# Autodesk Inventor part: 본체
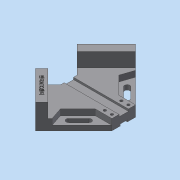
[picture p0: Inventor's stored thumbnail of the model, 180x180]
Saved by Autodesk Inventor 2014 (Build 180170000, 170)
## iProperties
Created: 2019-04
Part Number: 본체
Material: 일반
Document SubType Name: Modeling
Designer: 601-06
Density: 1 g/cm^3
Appearance: 기본값
Author: 601-06
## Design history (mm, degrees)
sketch "스케치4"
  geometry: L1 (-20, 0)-(0, 0); L2 (149.706, 0)-(114.35, -35.355); L3 (64.853, -84.853)-(0, -20); L4 (0, 0)-(0, -20); L5 (114.35, -35.355)-(93, -14.005); L6 (93, -14.005)-(93, 0); L7 (0, -20)-(-20, 0); L8 (114.35, -35.355)-(64.853, -84.853); L9 (93, 0)-(149.706, 0); L10 (0, 0)-(93, 0); L11 (93, 14.005)-(93, 0); L12 (114.35, 35.355)-(93, 14.005); L13 (114.35, 35.355)-(64.853, 84.853); L14 (64.853, 84.853)-(0, 20); L15 (0, 0)-(0, 20); 2 further points
  constraints: 30 end point, 12 perpendicular, 4 symmetric about line, 3 coincident, 3 horizontal
  dimensions: "d1" = 120 distance of L3.start L1.start; "d2" = 120 distance of L2.start L3.start; "d3" = 20 distance from line of L4 L1.start; "d5" = 93 distance between parallel lines of L4 L6; "d6" = 70 distance between parallel lines of L3 L5
extrude "돌출1" new body sketch "스케치4" distance "d7" = 18; taper "d8" = 0 deg
sketch "스케치5"
  geometry: L1 (-93, -14.005)-(-114.35, -35.355) reference; L2 (-114.35, -35.355)-(-64.853, -84.853) reference; L3 (-64.853, -84.853)-(0, -20) reference; L4 (0, 20)-(-64.853, 84.853) reference; L5 (-64.853, 84.853)-(-114.35, 35.355) reference; L6 (-114.35, 35.355)-(-93, 14.005) reference; L7 (-54.246, -74.246)-(-103.744, -24.749); L8 (-103.744, 24.749)-(-54.246, 74.246); 1 further point
  constraints: 4 end point, 4 point on line, 2 perpendicular
  dimensions: "d9" = 15 distance between parallel lines of L5 L8; "d10" = 15 distance between parallel lines of L2 L7
extrude "돌출2" join sketch "스케치5" distance "d11" = 24; taper "d12" = 0 deg
sketch "스케치6"
  geometry: L1 (-54.246, -74.246)-(0, -20) reference; L2 (0, -20)-(0, 20) reference; L3 (-93, 14.005)-(-93, -14.005) reference; L4 (-28.284, -20)-(-57.782, -49.497); L5 (-57.782, -49.497)-(-50.711, -70.711); L6 (0, -20)-(-28.284, -20); L7 (-114.35, -35.355)-(-64.853, -84.853) reference; 1 further point
  constraints: 6 end point, 2 point on line, 1 parallel, 1 perpendicular
  dimensions: "d13" = 20 distance between parallel lines of L4 L1; "d14" = 20 distance of L5.end L7.end; "d15" = 30 distance from line of L7 L4.end; "d16" = 20 distance from line of point (0, 0) L6
extrude "돌출3" cut sketch "스케치6" distance "d17" = 10; taper "d18" = 0 deg
sketch "스케치7"
  geometry: L1 (0, -20)-(-50.711, -70.711) reference; L2 (-26.669, -32.527)-(-43.64, -49.497); L3 (-29.851, -29.345)-(-46.822, -46.315); L4 (-40.458, -52.679)-(-23.487, -35.709); L5 (-114.35, -35.355)-(-64.853, -84.853) reference; A1 r 4.5 centre (-26.669, -32.527) between (-23.487, -35.709) and (-29.851, -29.345); A2 r 4.5 centre (-43.64, -49.497) between (-46.822, -46.315) and (-40.458, -52.679); 2 further points
  constraints: 8 end point, 4 point on circle, 4 tangent, 2 centre point, 2 parallel, 1 midpoint
  dimensions: "d19" = 9 distance between parallel lines of L3 L4; "d20" = 40 distance from line of L5 L2.end; "d21" = 24 distance of L2.start L2.end; "d22" = 10 distance between parallel lines of L1 L2
extrude "돌출4" cut sketch "스케치7" stored distance "d23" = 10; taper "d24" = 0 deg
sketch "스케치8"
  geometry: L1 (0, -20)-(0, 20) reference; C1 r 2.25 at (-6, -14); C2 r 2.25 at (-18, -14); 1 further point
  constraints: 2 centre point
  dimensions: "d25" = 4.5 diameter of C1; "d26" = 14 vertical distance of point (0, 0) C1.centre; "d27" = 6 distance from line of C1.centre L1; "d28" = 4.5 diameter of C2; "d29" = 14 vertical distance of point (0, 0) C2.centre; "d30" = 12 distance of C2.centre C1.centre
extrude "돌출5" cut sketch "스케치8" stored distance "d31" = 10; taper "d32" = 0 deg
sketch "스케치9"
  geometry: C1 r 2.25 at (-6, 14) reference; C2 r 2.25 at (-18, 14) reference; 1 further point
hole "구멍1" sketch "스케치9" at (-18, 14), (-6, 14) diameter "d33" = 8; stored, may be unused: countersink angle "d37" = 90 deg, drill point angle "d39" = 0 deg; dims "d34" = 6, "d35" = 4, "d36" = 2, "d38" = 10
sketch "스케치10"
  geometry: L1 (0, -20)-(0, 20) reference; L2 (-93, 14.005)-(-93, -14.005) reference; L3 (-93, -8)-(0, -8); L4 (0, -8)-(0, 8); L5 (0, 8)-(-93, 8); L6 (-93, 8)-(-93, -8); 1 further point
  constraints: 8 end point, 2 parallel, 2 point on line, 1 horizontal, 1 perpendicular
  dimensions: "d40" = 16 distance between parallel lines of L3 L5; "d41" = 8 distance from line of L5 point (0, 0)
extrude "돌출6" cut sketch "스케치10" distance "d42" = 3.5; taper "d43" = 0 deg
sketch "스케치11"
  geometry: L1 (0, 20)-(0, -20) reference; L2 (-93, -14.005)-(-93, 14.005) reference; L3 (-93, 6)-(0, 6); L4 (0, 6)-(0, -6); L5 (0, -6)-(-93, -6); L6 (-93, -6)-(-93, 6); 1 further point
  constraints: 8 end point, 2 parallel, 2 point on line, 1 horizontal, 1 perpendicular
  dimensions: "d44" = 12 distance between parallel lines of L3 L5; "d45" = 6 distance from line of point (0, 0) L5
extrude "돌출7" cut sketch "스케치11" distance "d46" = 3; taper "d47" = 0 deg
sketch "스케치12"
  geometry: L1 (-114.35, -35.355)-(-64.853, -84.853) reference; L2 (-64.853, -84.853)-(-54.246, -74.246) reference; 2 further points
  constraints: 1 other
  dimensions: "d48" = 35 distance from line of L2 point (-84.298, -54.801); "d50" = 7.5 distance from line of L1 point (-84.298, -54.801)
feature "엠보싱1" sketch "스케치12" dims "d1" = 120, "d2" = 120, "d3" = 20, "d5" = 93, "d6" = 70, "d51" = 0.5, "d52" = 0
node "솔리드1"
mirror "대칭1"
mirror "대칭2"
